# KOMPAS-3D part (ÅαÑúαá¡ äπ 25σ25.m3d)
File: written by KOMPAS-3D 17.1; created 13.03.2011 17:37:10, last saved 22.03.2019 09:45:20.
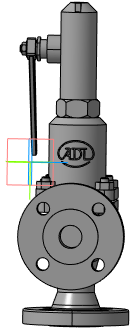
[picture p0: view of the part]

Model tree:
1. Ось X
2. Ось Y
3. Ось Z
4. Операция без истории:1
